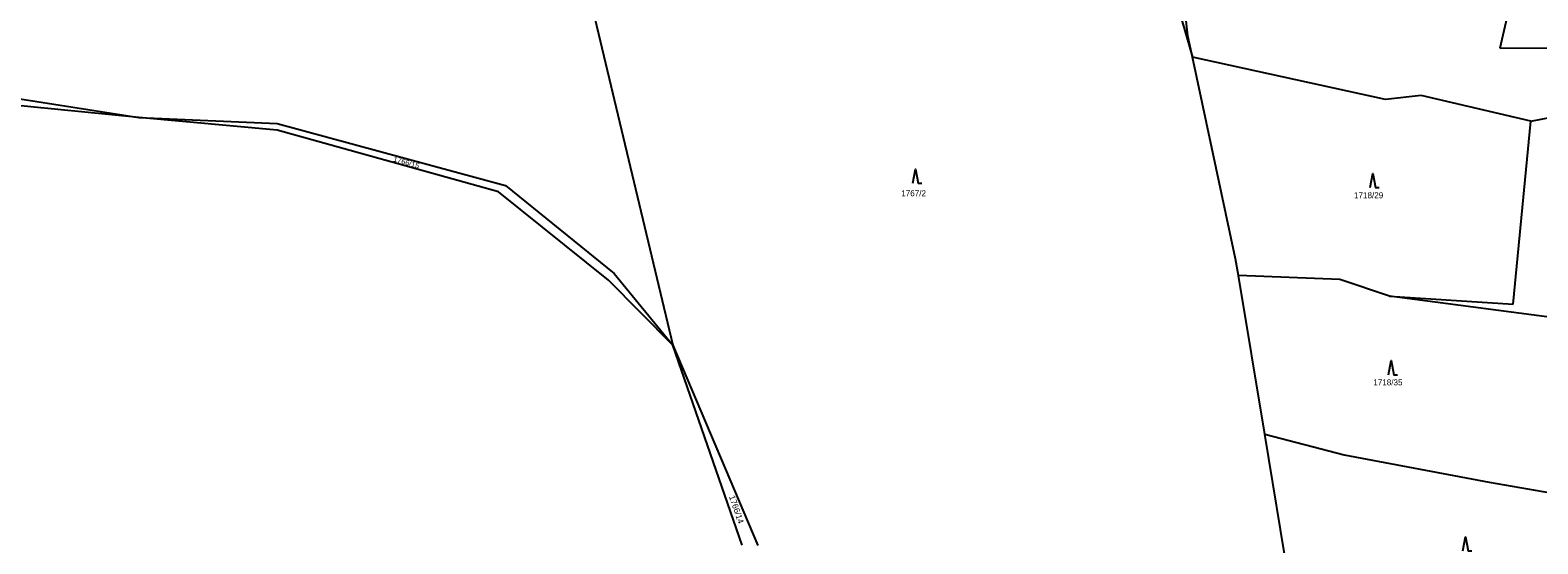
# Model space of a CAD drawing. Extents: x -609861 to -605046, y -1120287 to -1116307.
# Drawn here: x -609336.2 to -608912.5, y -1119002.8 to -1118858.4 of the extents above; entities that cross this region are included whole.
import ezdxf

# ---------------------------------------------------------------- set-up
doc = ezdxf.new("R2010")
doc.units = 0
for name, color, linetype in [('Vrstva 1', 7, 'Continuous'), ('Vrstva 2', 7, 'Continuous'), ('Vrstva 3', 7, 'Continuous')]:
    doc.layers.add(name, color=color, linetype=linetype)

msp = doc.modelspace()

# ---------------------------------------------------------------- linework, layer by layer
at = {"layer": 'Vrstva 1'}
for p, q in [((-608911.44, -1118811.9), (-608923.15, -1118863.4)), ((-609023.81, -1118816.51), (-609009.57, -1118865.99)), ((-609010.85, -1118860), (-609015.6, -1118816.54)), ((-609181.14, -1118839.96), (-609155.58, -1118946.92)), ((-609009.57, -1118865.99), (-609010.85, -1118860)), ((-608923.15, -1118863.4), (-608878.12, -1118863.36)), ((-608955.33, -1118877.9), (-609009.57, -1118865.99)), ((-608997.41, -1118922.65), (-609009.57, -1118865.99)), ((-609343.95, -1118876.97), (-609305.71, -1118882.96)), ((-608945.24, -1118876.71), (-608955.33, -1118877.9)), ((-608914.44, -1118883.92), (-608945.24, -1118876.71)), ((-608914.44, -1118883.92), (-608868.19, -1118875.15)), ((-609305.71, -1118882.96), (-609343.63, -1118879.14)), ((-609266.82, -1118886.51), (-609305.71, -1118882.96)), ((-609305.71, -1118882.96), (-609266.77, -1118884.65)), ((-609204.57, -1118903.79), (-609266.82, -1118886.51)), ((-609266.77, -1118884.65), (-609202.59, -1118902.08)), ((-608919.38, -1118935.37), (-608914.44, -1118883.92)), ((-609202.59, -1118902.08), (-609172.1, -1118926.76)), ((-609173.67, -1118928.63), (-609204.57, -1118903.79)), ((-608996.63, -1118927.35), (-608997.41, -1118922.65)), ((-609155.58, -1118946.92), (-609173.67, -1118928.63)), ((-609172.1, -1118926.76), (-609155.58, -1118946.92)), ((-608968.1, -1118928.42), (-608996.63, -1118927.35)), ((-608989.22, -1118971.97), (-608996.63, -1118927.35)), ((-608954.15, -1118933.18), (-608968.1, -1118928.42)), ((-608907.14, -1118939.34), (-608954.15, -1118933.18)), ((-608954.15, -1118933.18), (-608919.38, -1118935.37)), ((-609136.1, -1119003.13), (-609155.58, -1118946.92)), ((-609155.58, -1118946.92), (-609131.7, -1119003.25)), ((-608989.22, -1118971.97), (-608966.92, -1118977.75)), ((-608982.13, -1119014.72), (-608989.22, -1118971.97)), ((-608966.92, -1118977.75), (-608926.13, -1118985.41)), ((-608926.13, -1118985.41), (-608906.76, -1118988.82))]:
    msp.add_line(p, q, dxfattribs=at)
at = {"layer": 'Vrstva 3'}
for points in [[(-609088.13, -1118901.41), (-609087.38, -1118897.41), (-609086.63, -1118901.41), (-609085.63, -1118901.41)], [(-608959.6, -1118902.64), (-608958.85, -1118898.64), (-608958.1, -1118902.64), (-608957.1, -1118902.64)], [(-608954.46, -1118955.22), (-608953.71, -1118951.22), (-608952.96, -1118955.22), (-608951.96, -1118955.22)], [(-608933.55, -1119004.77), (-608932.8, -1119000.77), (-608932.05, -1119004.77), (-608931.05, -1119004.77)]]:
    msp.add_lwpolyline(points, dxfattribs=at)

# ---------------------------------------------------------------- texts
at = {"layer": 'Vrstva 2'}
for s, height, rotation, p in [('1766/15', 1.5, 343.77468, (-609234.287, -1118895.217)), ('1766/14', 1.7, 288.88532, (-609139.833, -1118989.472))]:
    msp.add_text(s, height=height, rotation=rotation, dxfattribs=at).set_placement(p)
for s, p in [('1767/2', (-609091.397, -1118905.08)), ('1718/29', (-608964.137, -1118905.64)), ('1718/35', (-608958.727, -1118958.22))]:
    msp.add_text(s, height=1.7, dxfattribs=at).set_placement(p)

doc.saveas('drawing.dxf')
